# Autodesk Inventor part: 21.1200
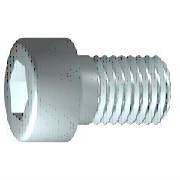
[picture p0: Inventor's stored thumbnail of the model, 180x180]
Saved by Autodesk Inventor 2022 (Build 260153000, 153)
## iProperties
Created: 2006-02
Part Number: 21.1200
Material: Steel, Mild
Description: M8 x 16 SHCS
Document SubType Name: Modeling
Standard: DIN 7984
Designer: Andy Moles
Standards Organization: DIN
Language: en-US
Size Designation: M8 x 16
Categories: <MemberInstance><Categories><Category DisplayName="Fasteners" InternalName="e4da775c-781d-43d5-af7c-5136215cf5a6" Mnemonic="FSTN"><Category DisplayName="Bolts"
Density: 7.85 g/cm^3
Mass: 10.6691 g
Surface Area: 9.17139 cm^2
Volume: 1.35912 cm^3
Vendor: S
Appearance: Zinc
Author: Andy Moles
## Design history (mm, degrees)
sketch "Sketch1"
  geometry: L1 (0.467, 0)-(16, 0); L2 (16, 0)-(16, 4); L3 (16, 4)-(3.75, 4); L4 (3.75, 4)-(2.983, 4); L5 (2.983, 4)-(0, 4); L6 (0, 4)-(0, 6.5); L7 (0, 6.5)-(-5, 6.5); L8 (-5, 6.5)-(-5, 2.887); L9 (-5, 2.887)-(-1.2, 2.887); L10 (-1.2, 2.887)-(0.467, 0); L11 (-9.2, 0)-(20.2, 0) reference; L12 (0, -1.3)-(0, 7.8) reference; L13 (3.75, 4)-(0, 4)
  constraints: 22 end point, 6 parallel, 2 collinear, 2 perpendicular, 1 horizontal, 1 point on line
  dimensions: "d1" = 12.25 distance from line of L3.end L2 (= GEL); "d2" = 0.76691 distance of L4.end L3.end (computed from GAL); "d3" = 5 distance between parallel lines of L8 L6 (= KOH); "d4" = 3.8 distance of L8.end L9.end (= INTI); "d5" = 60 deg angle of L10 L1; "d6" = 8 diameter of L3 L1 (= GD); "d7" = 8 diameter of L5 L1 (= BDM); "d8" = 5.7735 diameter of L9 L1 (= 1.1547 x SW); "d9" = 13 diameter of L7 L1 (= KOD); "d26" = 16 distance between parallel lines of L12 L2 (= NLG)
revolve "Body" sketch "Sketch1" stored, may be unused: angle "d10" = 90 deg
sketch "Sketch2"
  geometry: L1 (0, -9.1)-(0, 9.1) reference; L2 (-9.1, 0)-(9.1, 0) reference; L3 (2.887, 0)-(1.443, -2.5); L4 (1.443, -2.5)-(-1.443, -2.5); L5 (-1.443, -2.5)-(-2.887, 0); L6 (-2.887, 0)-(-1.443, 2.5); L7 (-1.443, 2.5)-(1.443, 2.5); L8 (1.443, 2.5)-(2.887, 0); 2 further points
  constraints: 12 end point, 1 coincident, 1 horizontal alignment, 1 point on line, 12 other
extrude "Slot" join sketch "Sketch2" stored distance "d11" = 10; taper "d12" = 0 deg
workplane "Work Plane1"
body "Solid1"
fillet "Fillet1" dims "d17" = 0.8 (= RR)
feature "Thread" dims "d13" = 16, "d14" = 0
chamfer "Chamfer1" distance "d15" = 0.76681 (= -0.5 x SPD + 0.5 x GD); stored, may be unused: second distance "d16" = 0.76681 (= GUL), angle "d27" = 45 deg
other parameters: "GD" = 8 (= NND) [user parameter; used in 2 equation terms], "NLG" = 16 [user parameter; used in 1 equation term], "GEL" = 12.25 [user parameter; used in 1 equation term], "KOD" = 13 [user parameter; used in 1 equation term], "KOH" = 5 [user parameter; used in 1 equation term], "INTI" = 3.8 [user parameter; used in 1 equation term], "GAL" = 0.76681 (= 0.61345 x PTC) [user parameter; used in 1 equation term], "GUL" = 0.76681 (= 0.61345 x PTC) [user parameter; used in 1 equation term], "BDM" = 8 (= NND) [user parameter; used in 1 equation term], "SW" = 5 [user parameter; used in 2 equation terms], "RR" = 0.8 [user parameter; used in 1 equation term], "SPD" = 6.46637 (= NND - 1.2269 x PTC) [user parameter; used in 1 equation term], "d19" = 0, "d28" = 0, "d29" = 0, "TOA" = 30 deg [user parameter], "GD1" = 6.46637 (= THREADDIA - 1.2269 x PTC) [user parameter], "THREADDIA" = 8 [user parameter; used in 1 equation term], "FAWI" = 45 deg [user parameter], "ANG" = 120 deg [user parameter], "TPU" = 8 (computed from PTC) [user parameter], "PTC" = 1.25 [user parameter; used in 5 equation terms], "NND" = 8 [user parameter; used in 3 equation terms], "E0" = 5.775 (= 1.155 x SW) [user parameter]
